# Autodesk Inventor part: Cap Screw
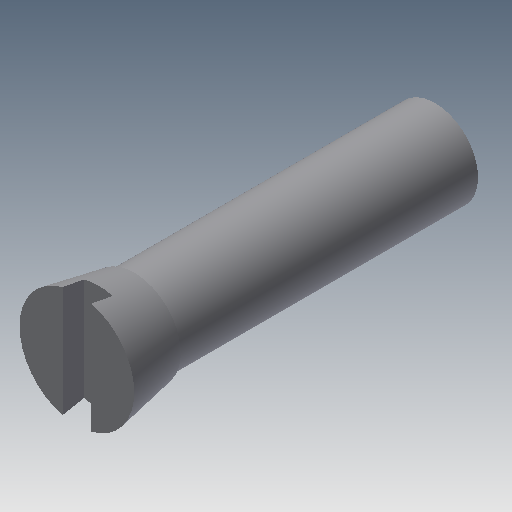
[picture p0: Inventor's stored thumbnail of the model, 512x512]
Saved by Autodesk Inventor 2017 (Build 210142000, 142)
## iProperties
Shininess: 77.0
Length Units: 11269
Angle Units: 11279
Time Units: 11290
Mass Units: 11283
Length Display Precision: 3
Angle Display Precision: 2
Created: 2002-02
Part Number: Cap Screw
Document SubType Name: Modeling
Designer: ***
Density: 1 g/cm^3
Material: Generic
Mass: 0.736586 g
Surface Area: 5.87035 cm^2
Volume: 0.736586 cm^3
Appearance: Default
Density: 0.0
Volumn: 0.0
Area: 0.0
PropertySet Name: Model Information
Control State: 0
Master: False
Checked Out: False
Author: ***
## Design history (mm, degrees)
sketch "Sketch1"
  geometry: L1 (0, 27.83)-(4, 27.83); L2 (4, 27.83)-(3.25, 23.83); L3 (3.25, 23.83)-(0, 23.83); L4 (0, 23.83)-(0, 27.83)
  constraints: 8 end point, 1 horizontal, 1 parallel, 1 perpendicular, 1 point on line
  dimensions: "d2" = 4 distance from line of L1 L2.end; "d5" = 8 diameter of L1.end L4; "d6" = 6.5 diameter of L3.start L4; "d14" = 4 distance of L3.end L1.start
revolve "Revolution1" sketch "Sketch1" stored, may be unused: angle "d7" = 90 deg
sketch "Sketch2"
  geometry: C1 r 3 at (0, 0)
  constraints: 1 centre point
  dimensions: "d8" = 6 diameter of C1
extrude "Extrusion1" join sketch "Sketch2" distance "d9" = 21; taper "d10" = 0 deg
sketch "Sketch3"
  geometry: L1 (-1, 28.967)-(1, 28.967); L2 (1, 28.967)-(1, 26.33); L3 (1, 26.33)-(-1, 26.33); L4 (-1, 26.33)-(-1, 28.967); L5 (-4, 27.83)-(4, 27.83) reference
  constraints: 8 end point, 2 parallel, 1 horizontal, 1 perpendicular
  dimensions: "d11" = 2 distance of L1.start L1.end; "d15" = 1.5 distance between parallel lines of L5 L3
extrude "Extrusion2" cut sketch "Sketch3" stored distance "d12" = 24; taper "d13" = 0 deg
body "Solid1"
